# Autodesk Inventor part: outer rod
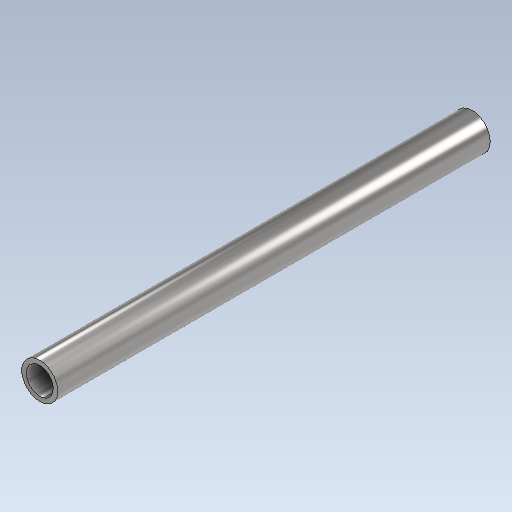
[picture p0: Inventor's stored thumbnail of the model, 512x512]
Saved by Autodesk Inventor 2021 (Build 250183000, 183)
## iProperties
Created: 2021-06
Part Number: outer rod
Material: Steel, Alloy
Document SubType Name: Modeling
Designer: adams
Density: 7.73 g/cm^3
Appearance: Semi-Polished
Author: adams
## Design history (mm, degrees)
sketch "Sketch1"
  geometry: 1 further point
sketch "Sketch2"
  geometry: C1 r 25.4 at (0, 0); 1 further point
  constraints: 1 centre point, 1 coincident
  dimensions: "d0" = 50.8 diameter of C1
extrude "Extrusion1" new body sketch "Sketch2" distance "d1" = 609.6; taper "d2" = 0 deg
sketch "Sketch3"
  geometry: C1 r 19.05 at (0, 0); 1 further point
  constraints: 1 centre point, 1 coincident
  dimensions: "d3" = 38.1 diameter of C1
extrude "Extrusion2" cut sketch "Sketch3" extent not by distance; stored distance "d4" = 0; taper "d5" = 0 deg
body "Solid1"
